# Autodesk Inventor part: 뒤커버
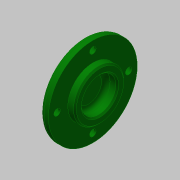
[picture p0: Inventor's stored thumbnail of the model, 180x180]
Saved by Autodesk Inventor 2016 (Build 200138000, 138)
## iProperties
Created: 2015-12
Part Number: 뒤커버
Document SubType Name: Modeling
Designer: mdu
Density: 2.71 g/cm^3
Material: 알루미늄 6061
Appearance: 진녹색
Mass: 56.1988 g
Surface Area: 84.0425 cm^2
Volume: 20.7376 cm^3
Author: mdu
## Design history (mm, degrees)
sketch "스케치1"
  geometry: L1 (-7, 0)-(7, 0); L2 (-7, 0)-(-7, 15.539); L3 (-7, 15.539)-(-4, 18.5); L4 (-4, 18.5)-(-4, 31); L5 (-4, 31)-(2, 31); L6 (2, 31)-(2, 17.5); L7 (2, 17.5)-(7, 17.5); L8 (7, 17.5)-(7, 0); 2 further points
  constraints: 16 end point, 4 parallel, 2 perpendicular, 1 coincident, 1 horizontal, 1 midpoint
  dimensions: "d0" = 14 distance of L1.start L1.end; "d1" = 62 diameter of L5 L1; "d2" = 35 diameter of L7 L1; "d3" = 37 diameter of L3.end L1; "d4" = 3 distance between parallel lines of L4 L2; "d5" = 6 distance of L4.end L5.end
revolve "회전1" sketch "스케치1" stored, may be unused: angle "d6" = 90 deg
sketch "스케치2" dims "d32" = 50
  geometry: 3 further points
  constraints: 2 vertical alignment, 1 coincident, 2 other
hole "구멍1" sketch "스케치2" at (0, 25) diameter "d8" = 4.5; stored, may be unused: countersink angle "d12" = 90 deg, drill point angle "d14" = 118 deg; dims "d9" = 6, "d10" = 8, "d11" = 4.4, "d13" = 8
hole "구멍2" diameter "d20" = 24; stored, may be unused: countersink angle "d24" = 90 deg, drill point angle "d26" = 0 deg; dims "d18" = 10, "d19" = 10, "d21" = 6, "d22" = 8, "d23" = 4.4, "d25" = 8
fillet "모깎기1" dims "d27" = 3
fillet "모깎기2" dims "d28" = 3
chamfer "모따기1" distance "d29" = 1; stored, may be unused: second distance "d30" = 2, angle "d31" = 45 deg
node "솔리드1"
pattern_circular "원형 패턴1" dims angle "d16" = 360 deg
